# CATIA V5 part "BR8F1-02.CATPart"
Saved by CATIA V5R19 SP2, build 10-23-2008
Part number: BR8F1-02
Definition: design
Nomenclature: BR8F1-02
Source: Unknown
Bounding box of the stored display mesh (mm): x -3.9 to 11.15, y 0 to 18.1, z 0 to 10.16
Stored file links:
  Z:\fausse table rondelle-20220905T211342Z-001\fausse table rondelle\BR8F1-02.CATPart
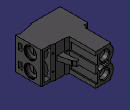
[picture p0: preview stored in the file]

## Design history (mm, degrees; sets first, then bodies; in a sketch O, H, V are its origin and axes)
AxisSystem1: origin (0, 0, 0), X (1, 0, 0), Y (0, 1, 0), Z (0, 0, 1)
Body1 "MANIFOLD_SOLID_BREP #36744" (main body)
  Solid1: solid without history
